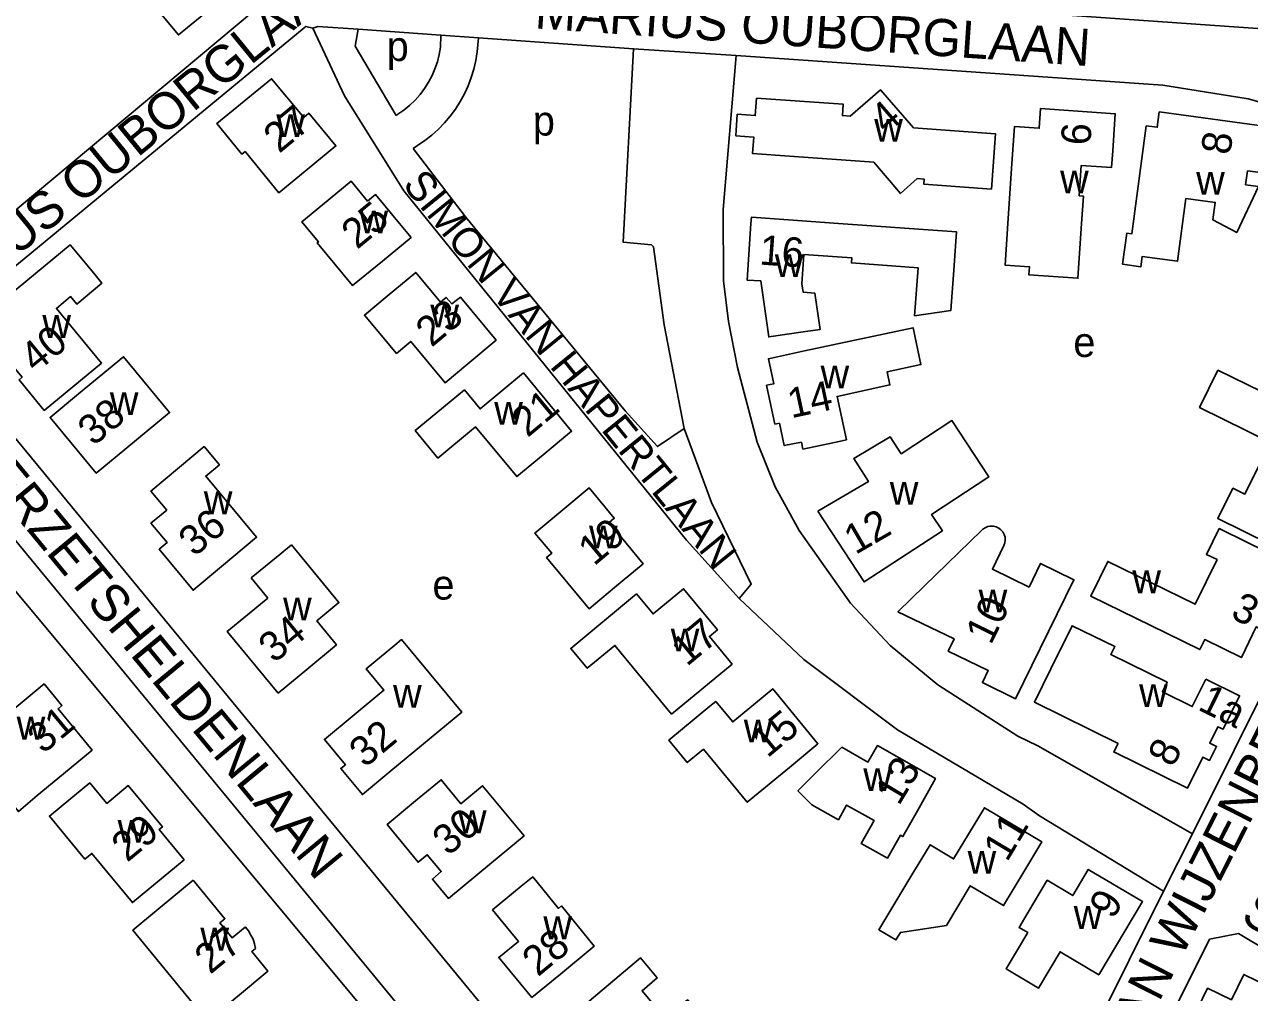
# Model space of a CAD drawing. Extents: x 156721 to 158827, y 386657 to 388950.
# Drawn here: x 158250 to 158415.3, y 387396.3 to 387526.8 of the extents above; entities that cross this region are included whole.
import ezdxf

# ---------------------------------------------------------------- set-up
doc = ezdxf.new("R2010")
doc.units = 0
for name, color, linetype in [('BLT_Basislijn', 7, 'Continuous'), ('BLT_Bebouwing', 7, 'Continuous'), ('BLT_Centroide', 7, 'Continuous'), ('BLT_Huisnummer', 7, 'Continuous'), ('BLT_Huisnummer_reeks', 7, 'Continuous'), ('BLT_Straatnaam', 7, 'Continuous'), ('BLT_Straatnaam_verkleind', 7, 'Continuous')]:
    doc.layers.add(name, color=color, linetype=linetype)

msp = doc.modelspace()

# ---------------------------------------------------------------- linework, layer by layer
at = {"layer": 'BLT_Basislijn'}
for p, q in [((158236.7, 387491.73), (158280.86, 387528.64)), ((158295.01, 387526.2), (158306.14, 387525.41)), ((158306.1, 387523.79), (158306.14, 387525.41)), ((158306.14, 387525.41), (158311.24, 387525.05)), ((158311.06, 387523.15), (158311.24, 387525.05)), ((158311.24, 387525.05), (158332.13, 387523.57)), ((158332.13, 387523.57), (158345.99, 387522.65)), ((158251.51, 387453.91), (158222.69, 387488.48)), ((158230.66, 387472.03), (158252.2, 387446.24)), ((158302.62, 387391.87), (158251.51, 387453.91)), ((158252.2, 387446.24), (158303.64, 387384.58)), ((158407.56, 387417.67), (158403.65, 387409.94))]:
    msp.add_line(p, q, dxfattribs=at)
for points in [[(158331.61, 387684.16), (158330.27, 387682.97), (158337.29, 387598.34), (158342.49, 387594.21), (158431.88, 387594.8), (158432.5, 387594.66), (158434.94, 387592.24), (158434.85, 387566.34), (158432.92, 387555.36), (158430.15, 387548.17), (158421.36, 387530.67), (158420.31, 387528.76), (158417.02, 387526.27), (158293.15, 387534.97), (158290, 387537.72), (158280.9, 387649.05), (158280.63, 387649.25), (158242.83, 387649.3)], [(158288.88, 387526.34), (158287.94, 387526.59), (158287.69, 387526.39), (158240.14, 387487.18), (158239.05, 387485.39), (158239.34, 387482.39), (158333.56, 387367.98), (158338.7, 387361.3), (158349.97, 387350.46), (158363.72, 387340.19), (158366.28, 387340.01), (158368.29, 387340.44), (158369.64, 387341.95), (158371.11, 387344.52), (158403.65, 387409.94)], [(158288.88, 387526.34), (158289.57, 387526.59), (158295.01, 387526.2)], [(158288.88, 387526.34), (158293.15, 387517.2), (158301.16, 387504.41), (158339.29, 387457.28), (158346.42, 387449.42)], [(158295.01, 387526.2), (158294.59, 387523.9), (158300.11, 387514.58)], [(158306.1, 387523.79), (158305.93, 387522.8), (158305.68, 387521.82), (158305.35, 387520.87), (158304.96, 387519.94), (158304.48, 387519.05), (158303.94, 387518.2), (158303.34, 387517.4), (158302.67, 387516.64), (158301.94, 387515.94), (158301.16, 387515.3), (158300.34, 387514.73), (158300.11, 387514.58)], [(158332.13, 387523.57), (158330.73, 387497.48), (158334.55, 387497.1), (158334.82, 387496.86), (158336.3, 387486.32), (158338.96, 387472.36)], [(158311.06, 387523.15), (158310.86, 387521.97), (158310.59, 387520.82), (158310.24, 387519.68), (158309.82, 387518.57), (158309.32, 387517.49), (158308.75, 387516.44), (158308.11, 387515.44), (158307.4, 387514.48), (158306.64, 387513.57), (158305.81, 387512.71), (158304.93, 387511.91), (158303.99, 387511.18), (158303.01, 387510.5), (158302.4, 387510.13)], [(158345.99, 387522.65), (158344.24, 387501.88), (158344.29, 387492.26), (158344.98, 387486.79), (158346.19, 387480.57), (158348.85, 387470.52), (158351.24, 387464.49), (158354.49, 387458.59), (158361.44, 387448.78), (158366.76, 387443.07), (158373.21, 387437.74), (158384, 387430.82), (158386.71, 387429.54), (158407.56, 387417.67)], [(158345.99, 387522.65), (158403.56, 387518.64), (158415.07, 387516.8), (158426.73, 387513.53), (158436.36, 387509.23), (158447.33, 387503.79), (158447.65, 387503.24), (158448.23, 387499.47), (158447.03, 387496.83), (158407.56, 387417.67)], [(158302.4, 387510.13), (158309.48, 387500.88), (158331.02, 387474.71), (158335.38, 387469.9), (158338.96, 387472.36)], [(158338.96, 387472.36), (158342.65, 387462.34), (158348.04, 387451.34), (158346.42, 387449.42)], [(158346.42, 387449.42), (158355.12, 387441.19), (158367.78, 387431.68), (158384.7, 387421.68), (158386.91, 387420.07), (158403.65, 387409.94)], [(158479.26, 387358.12), (158480.57, 387361.19), (158480.44, 387364.39), (158413.76, 387404.2), (158409.87, 387403.43), (158406.52, 387396.76), (158403.54, 387390.88), (158378.41, 387341.02), (158377.68, 387339.13), (158377.58, 387336.58), (158377.87, 387335.17), (158380.17, 387332.46), (158385.92, 387329.58), (158450.01, 387304.36), (158452.34, 387304.42), (158453.57, 387306.68), (158455.04, 387308.93)]]:
    msp.add_lwpolyline(points, dxfattribs=at)
at = {"layer": 'BLT_Bebouwing'}
msp.add_line((158271.51, 387414.14), (158267.65, 387410.95), dxfattribs=at)
for points in [[(158273.69, 387542.83), (158278.68, 387543.19), (158279.42, 387534.21), (158275.75, 387533.93), (158276.09, 387529.82), (158270.74, 387525.43), (158267.57, 387529.29), (158266.92, 387530.08), (158269.84, 387532.47), (158269.76, 387533.45), (158268.86, 387533.39), (158268.21, 387542.44), (158273.69, 387542.83)], [(158288.12, 387507.28), (158284.3, 387504.13), (158279.73, 387509.69), (158279.31, 387509.34), (158279.09, 387509.61), (158275.91, 387513.47), (158283.31, 387519.53), (158287.64, 387514.31), (158288.33, 387514.86), (158291.98, 387510.46), (158288.12, 387507.28)], [(158380.61, 387507.12), (158380.98, 387512.11), (158369.94, 387512.92), (158365.45, 387518.03), (158361.37, 387514.49), (158360.34, 387514.56), (158360.45, 387516.08), (158348.74, 387516.9), (158348.58, 387514.56), (158346.13, 387514.73), (158345.93, 387511.84), (158348.37, 387511.66), (158348.22, 387509.43), (158353.21, 387509.08), (158364.56, 387508.29), (158368.18, 387504.03), (158370.4, 387506.05), (158371.36, 387505.98), (158371.31, 387505.31), (158380.43, 387504.64), (158380.61, 387507.12)], [(158392.59, 387500), (158392.84, 387503.7), (158392.28, 387503.74), (158392.56, 387507.84), (158396.65, 387507.56), (158396.81, 387509.82), (158397.14, 387514.81), (158387.08, 387515.53), (158386.88, 387512.84), (158383.55, 387513.09), (158383.21, 387508.1), (158382.66, 387500), (158382.28, 387494.38), (158385.58, 387494.16), (158385.5, 387493.06), (158392.1, 387492.61), (158392.59, 387500)], [(158298.26, 387494.93), (158302.12, 387498.11), (158300.56, 387500), (158297.34, 387503.9), (158296.26, 387503.02), (158294.03, 387505.71), (158290.17, 387502.53), (158287.39, 387500.24), (158287.59, 387500), (158289.63, 387497.52), (158289.48, 387497.4), (158294.24, 387491.62), (158298.26, 387494.93)], [(158355.34, 387485.41), (158357.32, 387485.7), (158356.6, 387490.61), (158355.04, 387490.72), (158354.84, 387491.84), (158355.13, 387495.82), (158361.59, 387495.37), (158361.54, 387494.68), (158370.54, 387494.03), (158370.07, 387487.55), (158374.96, 387488.26), (158375.35, 387493.68), (158375.73, 387498.85), (158359.8, 387500), (158353.04, 387500.49), (158348.05, 387500.85), (158347.99, 387500), (158347.47, 387492.36), (158349.31, 387492.24), (158350.39, 387484.69), (158355.34, 387485.41)], [(158259.32, 387493.29), (158256.13, 387497.14), (158246.79, 387489.39), (158247.6, 387488.41), (158244.33, 387485.68), (158246.54, 387483.01), (158246.22, 387482.75), (158247.24, 387481.51), (158247.56, 387481.78), (158249.65, 387479.25), (158249.23, 387478.91), (158252.63, 387474.79), (158256.49, 387477.97), (158260.36, 387481.16), (158254.27, 387488.54), (158256.19, 387490.13), (158257.01, 387489.13), (158260.42, 387491.95), (158259.32, 387493.29)], [(158309.77, 387481.07), (158313.61, 387484.27), (158308.78, 387490.07), (158307.65, 387489.14), (158306.86, 387490.03), (158306.08, 387489.4), (158302.75, 387493.4), (158298.91, 387490.2), (158295.85, 387487.65), (158300.17, 387482.48), (158302.08, 387484.08), (158306.71, 387478.52), (158309.77, 387481.07)], [(158359.9, 387470.61), (158355.01, 387469.56), (158354.79, 387470.49), (158352.49, 387470.04), (158351.83, 387473.05), (158351.22, 387472.94), (158350.1, 387478.17), (158351.06, 387478.36), (158350.34, 387481.75), (158355.23, 387482.8), (158369.86, 387485.94), (158370.93, 387480.96), (158366.36, 387479.98), (158366.74, 387478.22), (158359.61, 387476.68), (158360.87, 387470.82), (158359.9, 387470.61)], [(158263.5, 387469.49), (158259.64, 387466.31), (158253.41, 387473.84), (158257.27, 387477.02), (158263.33, 387482.03), (158269.55, 387474.49), (158263.5, 387469.49)], [(158319.94, 387468.78), (158323.79, 387471.97), (158317.29, 387479.83), (158311.43, 387474.99), (158309.33, 387477.54), (158305.47, 387474.35), (158302.7, 387472.06), (158305.76, 387468.36), (158310.84, 387472.56), (158316.39, 387465.85), (158319.94, 387468.78)], [(158420.82, 387475.39), (158425.32, 387473.19), (158424.24, 387470.93), (158428.6, 387468.87), (158424.75, 387460.89), (158425.81, 387460.35), (158424.8, 387458.25), (158424.43, 387458.43), (158422.5, 387454.54), (158418.01, 387456.74), (158410.98, 387460.18), (158413.01, 387464.29), (158414.64, 387463.49), (158418.09, 387470.46), (158408.52, 387475.19), (158411, 387480.19), (158420.82, 387475.39)], [(158276.56, 387453.72), (158272.72, 387450.52), (158268.14, 387456.06), (158269.21, 387456.96), (158267.03, 387459.56), (158269.17, 387461.34), (158267.03, 387463.91), (158270.87, 387467.11), (158274.21, 387469.9), (158276.26, 387467.45), (158274.42, 387465.92), (158281.29, 387457.67), (158276.56, 387453.72)], [(158329.6, 387450.9), (158326.15, 387448.03), (158320.42, 387454.93), (158321.12, 387455.51), (158318.85, 387458.24), (158322.32, 387461.13), (158326.17, 387464.32), (158329.55, 387460.24), (158328.86, 387459.65), (158333.44, 387454.1), (158329.6, 387450.9)], [(158382.13, 387456.57), (158382.25, 387456.93), (158382.3, 387457.31), (158382.27, 387457.69), (158382.16, 387458.06), (158381.97, 387458.39), (158381.72, 387458.68), (158381.42, 387458.91), (158381.07, 387459.08), (158380.7, 387459.16), (158380.31, 387459.17), (158379.94, 387459.1), (158379.59, 387458.95), (158379.27, 387458.74), (158379.11, 387458.58)], [(158382.13, 387456.57), (158380.56, 387453.37), (158385.51, 387450.94), (158387.08, 387454.14), (158391.57, 387451.94), (158385.9, 387440.38), (158383.7, 387435.89), (158379.22, 387438.07), (158380.01, 387439.69), (158374.6, 387442.32), (158375.39, 387443.95), (158367.83, 387447.62), (158371.42, 387451.11), (158379.11, 387458.58)], [(158415, 387456.97), (158419.49, 387454.77), (158417.89, 387451.52), (158418.91, 387451.02), (158417.71, 387448.59), (158419.03, 387447.99), (158419.28, 387447.14), (158418.35, 387445.22), (158417.5, 387444.95), (158416.18, 387445.59), (158414.16, 387441.43), (158409.21, 387443.86), (158408.55, 387442.51), (158404.06, 387444.71), (158393.84, 387449.73), (158396.14, 387454.41), (158407.93, 387448.63), (158410.88, 387454.65), (158409.45, 387455.35), (158411.17, 387458.85), (158415, 387456.97)], [(158288.06, 387439.84), (158292.06, 387443.14), (158289.4, 387446.38), (158292.39, 387448.85), (158285.98, 387456.64), (158284.42, 387455.36), (158280.56, 387452.18), (158282.79, 387449.47), (158277.32, 387444.96), (158284.2, 387436.66), (158288.06, 387439.84)], [(158332.55, 387450.02), (158323.67, 387442.67), (158325.91, 387439.99), (158329.64, 387443.07), (158337.27, 387433.82), (158345.45, 387440.57), (158342.38, 387444.29), (158343.46, 387445.18), (158338.89, 387450.72), (158334.78, 387447.32), (158332.55, 387450.02)], [(158409.36, 387438.54), (158407.54, 387434.83), (158403.5, 387436.82), (158404.14, 387438.12), (158396.56, 387441.84), (158397.09, 387442.92), (158391.33, 387445.74), (158388.46, 387439.9), (158386.25, 387435.41), (158397.52, 387429.84), (158396.95, 387428.71), (158406.88, 387423.81), (158408.95, 387428.02), (158409.88, 387427.56), (158410.81, 387429.45), (158409.89, 387429.9), (158410.97, 387432.1), (158411.69, 387431.76), (158413.93, 387436.29), (158409.36, 387438.54)], [(158299.92, 387443.11), (158300.84, 387443.87), (158308.97, 387434.06), (158299.42, 387426.15), (158295.57, 387422.96), (158292.65, 387426.49), (158293.26, 387426.99), (158290.44, 387430.39), (158298.46, 387437.04), (158296.07, 387439.92), (158299.92, 387443.11)], [(158255.23, 387425.77), (158259.09, 387428.96), (158254.49, 387434.53), (158255.02, 387434.98), (158252.61, 387437.89), (158247.21, 387433.41), (158244.98, 387436.1), (158241.12, 387432.92), (158239.14, 387431.28), (158243.6, 387425.89), (158244.34, 387426.5), (158249.14, 387420.67), (158251.69, 387422.85), (158255.23, 387425.77)], [(158353.18, 387426.62), (158357.03, 387429.81), (158350.92, 387437.23), (158348.6, 387435.31), (158345.53, 387432.77), (158343.24, 387435.53), (158342.45, 387434.87), (158336.91, 387430.3), (158339.4, 387427.28), (158341.57, 387429.07), (158347.49, 387421.92), (158353.18, 387426.62)], [(158370.44, 387420.78), (158372.89, 387425.14), (158365.05, 387429.57), (158363.77, 387427.33), (158360.25, 387429.35), (158356.71, 387425.83), (158354.32, 387423.45), (158356.2, 387421.57), (158359.78, 387419.56), (158360.9, 387421.55), (158364.63, 387419.46), (158362.87, 387416.34), (158366.41, 387414.36), (158368.16, 387417.48), (158368.49, 387417.29), (158370.44, 387420.78)], [(158267.65, 387410.95), (158264.53, 387408.38), (158259.06, 387415.01), (158258.13, 387414.25), (158253.33, 387420.06), (158254.92, 387421.36), (158258.78, 387424.54), (158261.08, 387421.77), (158263.96, 387424.16), (158268.57, 387418.59), (158268.16, 387418.26), (158271.51, 387414.14)], [(158312.99, 387413.76), (158307.17, 387408.94), (158305, 387411.56), (158306.21, 387412.56), (158304.31, 387414.85), (158303.08, 387413.83), (158298.89, 387418.92), (158302.74, 387422.11), (158306.19, 387424.96), (158308.86, 387421.73), (158311.78, 387424.14), (158317.38, 387417.37), (158312.99, 387413.76)], [(158384.66, 387412.31), (158382.08, 387407.98), (158377.57, 387410.66), (158374.36, 387405.28), (158368.16, 387404.36), (158367.55, 387403.35), (158365.26, 387404.73), (158369.58, 387411.91), (158372.16, 387416.2), (158375.33, 387414.28), (158379.5, 387421.19), (158387.22, 387416.6), (158384.66, 387412.31)], [(158385.4, 387407.09), (158384.17, 387405.02), (158385.33, 387404.33), (158382.42, 387399.46), (158386.79, 387396.86), (158389.71, 387401.76), (158394.92, 387398.65), (158400.81, 387408.52), (158393.51, 387412.86), (158391.4, 387409.33), (158387.96, 387411.39), (158385.4, 387407.09)], [(158281.14, 387402.18), (158280.66, 387401.79), (158282.81, 387399.15), (158278.96, 387395.96), (158274.66, 387392.41), (158264.58, 387404.66), (158265.41, 387405.35), (158272.73, 387411.39)], [(158272.73, 387411.39), (158277.01, 387406.21), (158276.33, 387405.65), (158277.98, 387403.64), (158279.74, 387405.09)], [(158322.29, 387398.75), (158318.43, 387395.57), (158313.97, 387400.98), (158316.62, 387403.16), (158313.13, 387407.4), (158316.99, 387410.58), (158318.54, 387411.84), (158322.02, 387407.6), (158322.41, 387407.93), (158326.85, 387402.52), (158322.29, 387398.75)], [(158281.14, 387402.18), (158281.01, 387402.81), (158280.81, 387403.43), (158280.53, 387404.01), (158280.19, 387404.56), (158279.78, 387405.06), (158279.74, 387405.09)], [(158335.89, 387386.07), (158335.09, 387386.94), (158330.23, 387382.85), (158327.06, 387386.6), (158328.07, 387387.47), (158323.52, 387392.86), (158327.34, 387396.09), (158333.07, 387400.94), (158335.35, 387398.22), (158333.29, 387396.49), (158336.42, 387392.76), (158339.41, 387395.27), (158342.61, 387391.47), (158335.89, 387386.07)], [(158424.37, 387393.2), (158418.53, 387381.25), (158411.9, 387384.48), (158413.52, 387387.8), (158406.8, 387391.08), (158409.61, 387396.84), (158412.82, 387395.27), (158414.49, 387398.69), (158418, 387396.97), (158417.74, 387396.43), (158424.37, 387393.2)]]:
    msp.add_lwpolyline(points, dxfattribs=at)
for points in [[(158403.08, 387515.06), (158418.22, 387513.01), (158417.37, 387506.78), (158415, 387507.1), (158414.74, 387505.22), (158416.46, 387504.99), (158413.53, 387498.78), (158410.32, 387500.48), (158410.64, 387502.83), (158406.69, 387503.37), (158405.55, 387494.91), (158400.79, 387495.55), (158400.61, 387494.16), (158398.13, 387494.49), (158398.69, 387498.67), (158399.37, 387498.58), (158401.33, 387513.17), (158402.8, 387512.98)], [(158357, 387461.21), (158363.84, 387465.18), (158361.86, 387468.28), (158366.79, 387471.21), (158368.28, 387468.94), (158375.11, 387473.41), (158380.08, 387465.81), (158372.37, 387460.76), (158373.82, 387458.55), (158363.26, 387451.64)]]:
    msp.add_lwpolyline(points, close=True, dxfattribs=at)

# ---------------------------------------------------------------- texts
at = {"layer": 'BLT_Centroide'}
for s, p in [('p', (158298.84, 387521.92)), ('w', (158283.94, 387511.66)), ('p', (158318.56, 387511.86)), ('w', (158364.62, 387511.03)), ('w', (158389.7, 387504.06)), ('w', (158408.06, 387503.88)), ('w', (158295.17, 387498.66)), ('w', (158351.2, 387492.78)), ('w', (158304.73, 387485.97)), ('w', (158252.38, 387484.56)), ('e', (158391.49, 387481.99)), ('w', (158357.38, 387477.75)), ('w', (158261.48, 387474.16)), ('w', (158313.35, 387472.84)), ('w', (158366.72, 387462.06)), ('w', (158274.16, 387460.78)), ('w', (158326.14, 387456.17)), ('e', (158305.01, 387449.26)), ('w', (158399.45, 387450.12)), ('w', (158284.86, 387446.45)), ('w', (158378.71, 387447.53)), ('w', (158337.17, 387442.28)), ('w', (158299.7, 387434.66)), ('w', (158400.36, 387434.78)), ('w', (158248.91, 387430.38)), ('w', (158347.02, 387430)), ('w', (158363.14, 387423.44)), ('w', (158262.53, 387416.47)), ('w', (158308.45, 387417.75)), ('w', (158377.22, 387412.28)), ('w', (158391.54, 387404.84)), ('w', (158319.98, 387403.45)), ('w', (158273.7, 387401.91))]:
    msp.add_text(s, height=4, dxfattribs=at).set_placement(p)
at = {"layer": 'BLT_Huisnummer'}
for s, rotation, p in [('27', 39.4898, (158284.33, 387509.37)), ('4', 40.8925, (158366.26, 387511.95)), ('6', 86.1758, (158393.78, 387510.46)), ('8', 82.2297, (158412.65, 387509.15)), ('25', 39.4886, (158294.84, 387496.41)), ('16', 355.8597, (158349.04, 387494.47)), ('23', 39.8232, (158304.89, 387483.21)), ('40', 39.499, (158251.48, 387479.73)), ('21', 39.6031, (158317.84, 387471.04)), ('14', 12.1324, (158353.42, 387473.71)), ('38', 39.5439, (158259.27, 387469.87)), ('36', 39.832, (158272.89, 387454.93)), ('12', 30.1187, (158362.08, 387455.25)), ('19', 39.7821, (158326.81, 387453.71)), ('10', 63.8887, (158380.36, 387443.03)), ('3', 333.8627, (158412.54, 387446.87)), ('34', 39.499, (158283.65, 387440.58)), ('17', 39.5398, (158339.33, 387440.15)), ('31', 39.562, (158252.48, 387428.34)), ('15', 39.588, (158350.2, 387427.8)), ('32', 39.6381, (158295.9, 387426.47)), ('13', 59.173, (158367.95, 387421.33)), ('30', 39.5635, (158307.13, 387414.58)), ('29', 39.5186, (158263.82, 387413.73)), ('11', 59.173, (158382.54, 387413.75)), ('9', 59.173, (158396.84, 387406)), ('27', 39.5714, (158275.03, 387398.62)), ('28', 39.5312, (158319.24, 387398.29))]:
    msp.add_text(s, height=4, rotation=rotation, dxfattribs=at).set_placement(p)
at = {"layer": 'BLT_Huisnummer_reeks'}
for s, rotation, p in [('1a', 333.8422, (158408.14, 387434.47)), ('8', 63.2325, (158404.93, 387426.5))]:
    msp.add_text(s, height=4, rotation=rotation, dxfattribs=at).set_placement(p)
at = {"layer": 'BLT_Straatnaam'}
for s, rotation, p in [('MARIUS OUBORGLAAN', 39.24, (158235.88, 387484.86)), ('MARIUS OUBORGLAAN', 356.1063, (158318.74, 387526.32)), ('VERZETSHELDENLAAN', 309.5367, (158241.41, 387469.34)), ('MAAN WIJZENBEEKLAAN', 63.1089, (158396.51, 387381.96)), ('SIMON VAN HAPERTLAAN', 329.5682, (158413.89, 387405.92))]:
    msp.add_text(s, height=5, rotation=rotation, dxfattribs=at).set_placement(p)
at = {"layer": 'BLT_Straatnaam_verkleind'}
msp.add_text('SIMON VAN HAPERTLAAN', height=4, rotation=309.0716, dxfattribs=at).set_placement((158300.88, 387505.16))

doc.saveas('drawing.dxf')
